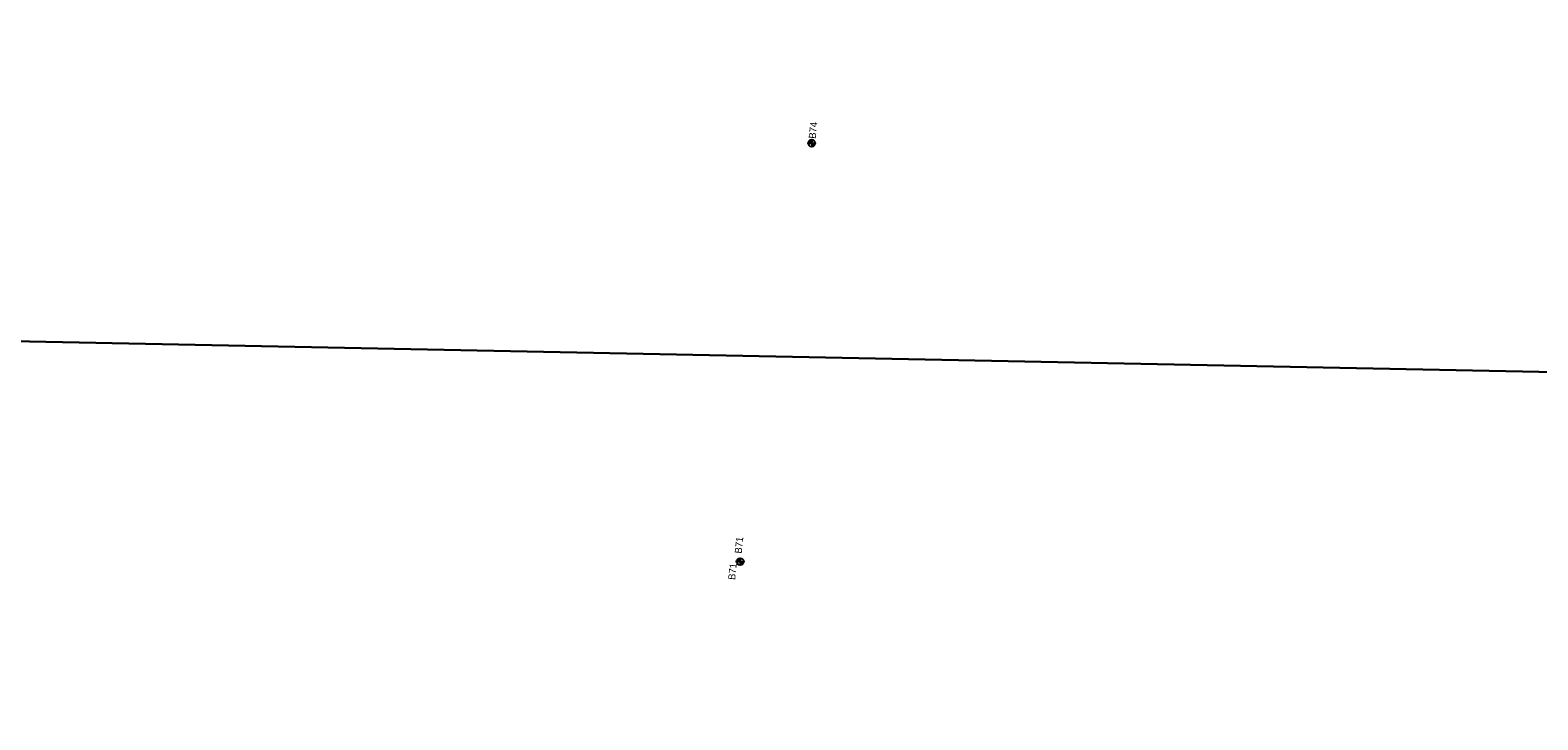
# Model space of a CAD drawing. Extents: x 335726 to 369746, y 119154 to 200788.
# Drawn here: x 358718 to 360859, y 169828 to 170808 of the extents above; entities that cross this region are included whole.
import ezdxf

# ---------------------------------------------------------------- set-up
doc = ezdxf.new("R2010")
doc.units = 0
for name, color, linetype in [('E_SOIL_BORE1 [KAPUR_CADDS_LEVELS]', 7, 'Continuous'), ('E_SOIL_BORE2 [KAPUR_CADDS_LEVELS]', 7, 'Continuous'), ('P_MARK', 7, 'Continuous'), ('P_RDWY_Text', 7, 'Continuous'), ('PLT_Sheet_Border', 7, 'Continuous')]:
    doc.layers.add(name, color=color, linetype=linetype)

msp = doc.modelspace()

# ---------------------------------------------------------------- linework, layer by layer
at = {"layer": 'P_MARK'}
for p, q in [((359823, 170647.5), (359833, 170647.5)), ((359828, 170652.5), (359828, 170642.5)), ((359721.4, 170053), (359731.4, 170053)), ((359726.4, 170058), (359726.4, 170048))]:
    msp.add_line(p, q, dxfattribs=at)
for centre in [(359828, 170647.5), (359726.4, 170053)]:
    msp.add_circle(centre, 5, dxfattribs=at)
for centre, radius, start, end in [((359828, 170647.5), 4.5, 89.9869, 179.9869), ((359828, 170647.5), 4, 89.9869, 179.9869), ((359828, 170647.5), 3.5, 89.9869, 179.9869), ((359828, 170647.5), 3, 89.9869, 179.9869), ((359828, 170647.5), 2.5, 89.9869, 179.9869), ((359828, 170647.5), 2, 89.9869, 179.9869), ((359828, 170647.5), 1.5, 89.9869, 179.9869), ((359828, 170647.5), 1, 89.9869, 179.9869), ((359828, 170647.5), 0.5, 89.9869, 179.9869), ((359828, 170647.5), 4.5, 269.9869, 359.9869), ((359828, 170647.5), 4, 269.9869, 359.9869), ((359828, 170647.5), 3.5, 269.9869, 359.9869), ((359828, 170647.5), 3, 269.9869, 359.9869), ((359828, 170647.5), 2.5, 269.9869, 359.9869), ((359828, 170647.5), 2, 269.9869, 359.9869), ((359828, 170647.5), 1.5, 269.9869, 359.9869), ((359828, 170647.5), 1, 269.9869, 359.9869), ((359828, 170647.5), 0.5, 269.9869, 359.9869), ((359726.4, 170053), 4.5, 89.9869, 179.9869), ((359726.4, 170053), 4, 89.9869, 179.9869), ((359726.4, 170053), 3.5, 89.9869, 179.9869), ((359726.4, 170053), 3, 89.9869, 179.9869), ((359726.4, 170053), 2.5, 89.9869, 179.9869), ((359726.4, 170053), 2, 89.9869, 179.9869), ((359726.4, 170053), 1.5, 89.9869, 179.9869), ((359726.4, 170053), 1, 89.9869, 179.9869), ((359726.4, 170053), 0.5, 89.9869, 179.9869), ((359726.4, 170053), 4.5, 269.9869, 359.9869), ((359726.4, 170053), 4, 269.9869, 359.9869), ((359726.4, 170053), 3.5, 269.9869, 359.9869), ((359726.4, 170053), 3, 269.9869, 359.9869), ((359726.4, 170053), 2.5, 269.9869, 359.9869), ((359726.4, 170053), 2, 269.9869, 359.9869), ((359726.4, 170053), 1.5, 269.9869, 359.9869), ((359726.4, 170053), 1, 269.9869, 359.9869), ((359726.4, 170053), 0.5, 269.9869, 359.9869)]:
    msp.add_arc(centre, radius, start, end, dxfattribs=at)
at = {"layer": 'P_RDWY_Text'}
msp.add_lwpolyline([(335725.8, 119818.4), (336752.7, 170808.1), (369746, 170143.6), (368719.1, 119153.9)], close=True, dxfattribs=at)
at = {"layer": 'PLT_Sheet_Border'}
msp.add_lwpolyline([(368719.1, 119153.9), (369746, 170143.6), (336752.7, 170808.1), (335725.8, 119818.4)], close=True, dxfattribs=at)

# ---------------------------------------------------------------- texts
at = {"layer": 'E_SOIL_BORE1 [KAPUR_CADDS_LEVELS]'}
for s, p in [('B74', (359833.6, 170653.4)), ('B71', (359728.5, 170064.1))]:
    msp.add_text(s, height=10, rotation=84.1728, dxfattribs=at).set_placement(p)
at = {"layer": 'E_SOIL_BORE2 [KAPUR_CADDS_LEVELS]'}
msp.add_text('B71', height=10, rotation=84.1728, dxfattribs=at).set_placement((359719.2, 170026.7))

doc.saveas('drawing.dxf')
